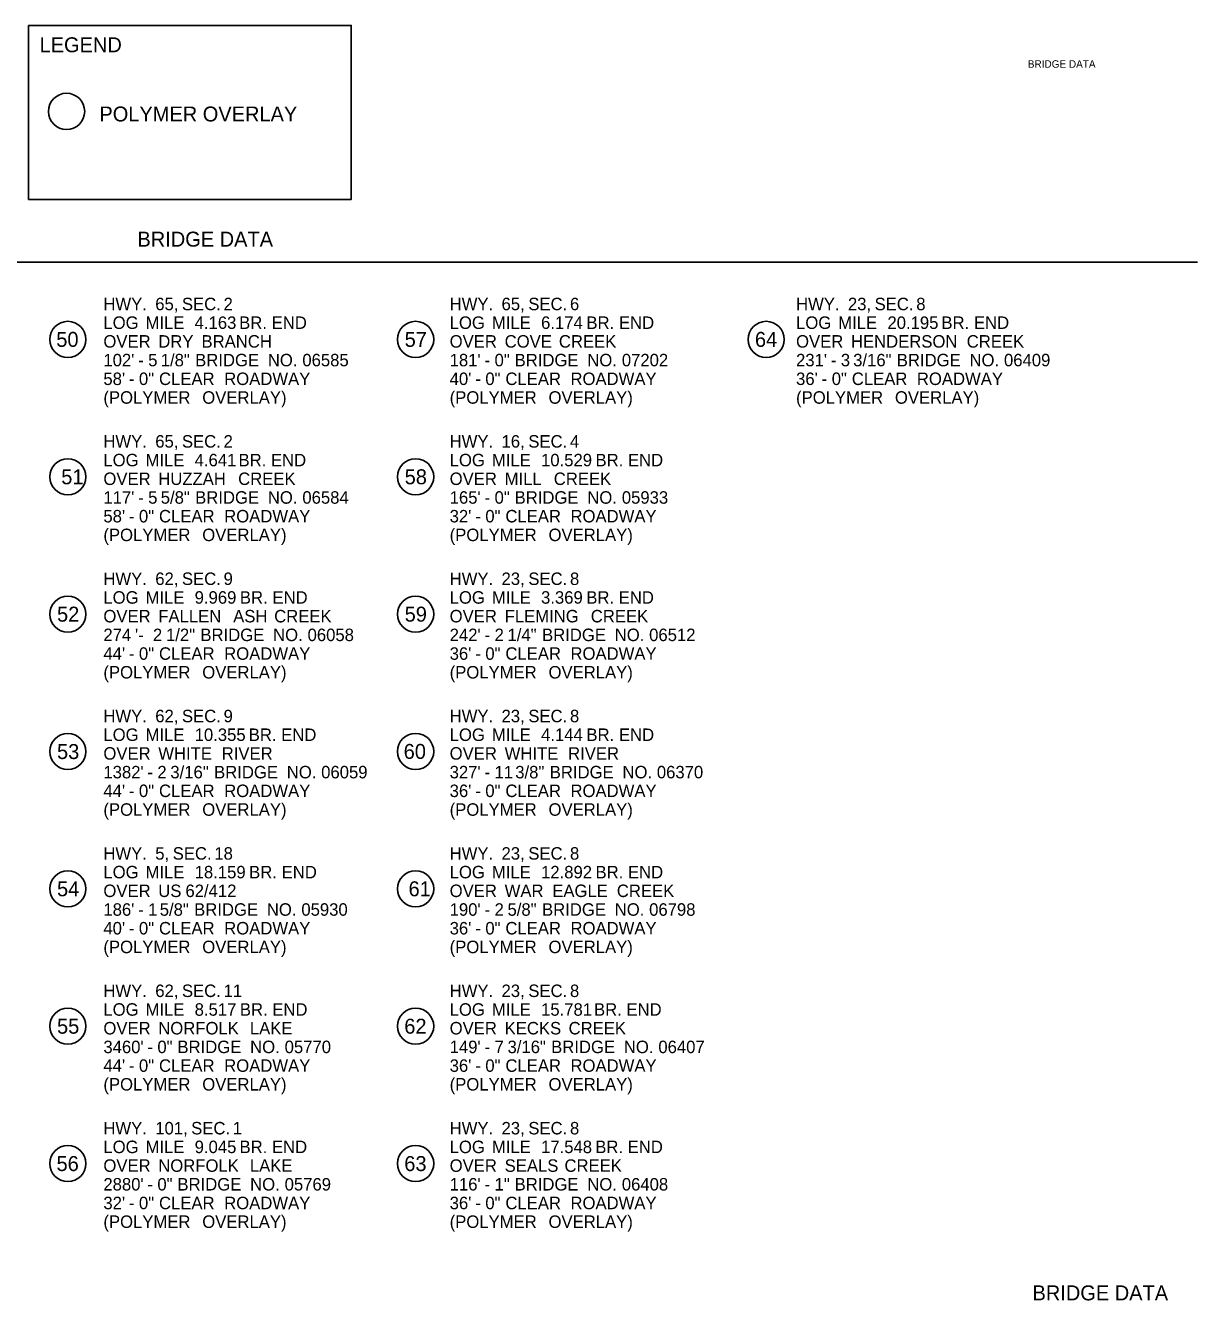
# Model space of a CAD drawing. Extents: x 1930546 to 1934225, y 596452 to 599553.
# Drawn here: x 1933284 to 1934225, y 598531 to 599553 of the extents above; entities that cross this region are included whole.
import ezdxf

# ---------------------------------------------------------------- set-up
doc = ezdxf.new("R2010")
doc.units = 0
for name, color, linetype in [('Default', 7, 'Continuous'), ('R_Border', 7, 'Continuous'), ('S_AREA_CALC', 7, 'Continuous')]:
    doc.layers.add(name, color=color, linetype=linetype)

msp = doc.modelspace()

# ---------------------------------------------------------------- linework, layer by layer
at = {"layer": 'R_Border'}
msp.add_line((1934224.6, 599363.5), (1932629.2, 599363.5), dxfattribs=at)
msp.add_lwpolyline([(1933286.8, 599553.3), (1933545.7, 599553.3), (1933545.7, 599413.8), (1933286.8, 599413.8)], close=True, dxfattribs=at)
for centre in [(1933317.3, 599484.4), (1933318.3, 599301.5), (1933597.3, 599301.5), (1933878.5, 599301.5), (1933318.3, 599191.3), (1933597.3, 599191.3), (1933318.3, 599081.1), (1933597.3, 599081.1), (1933318.3, 598970.9), (1933597.3, 598971), (1933318.3, 598860.8), (1933597.3, 598860.8), (1933318.3, 598750.6), (1933597.3, 598750.6), (1933318.3, 598640.4), (1933597.3, 598640.4)]:
    msp.add_circle(centre, 14.5, dxfattribs=at)

# ---------------------------------------------------------------- texts
at = {"layer": 'Default'}
for s, p in [('HWY.', (1933346.8, 599324.9)), (' 65,', (1933384.7, 599324.9)), (' SEC.', (1933406.1, 599324.9)), (' 2', (1933439.5, 599324.9)), ('HWY.', (1933624.6, 599324.9)), (' 65,', (1933662.5, 599324.9)), (' SEC.', (1933684, 599324.9)), (' 6', (1933717.4, 599324.9)), ('HWY.', (1933902.5, 599324.9)), (' 23,', (1933940.4, 599324.9)), (' SEC.', (1933961.8, 599324.9)), (' 8', (1933995.2, 599324.9)), ('LOG', (1933346.8, 599309.9)), (' MILE', (1933376.9, 599309.9)), (' 4.163', (1933416.3, 599309.9)), (' BR.', (1933452, 599309.9)), (' END', (1933478.1, 599309.9)), ('LOG', (1933624.6, 599309.9)), (' MILE', (1933654.8, 599309.9)), (' 6.174', (1933694.2, 599309.9)), (' BR.', (1933730.6, 599309.9)), (' END', (1933756.7, 599309.9)), ('LOG', (1933902.5, 599309.9)), (' MILE', (1933932.6, 599309.9)), (' 20.195', (1933972.1, 599309.9)), (' BR.', (1934015.4, 599309.9)), (' END', (1934041.5, 599309.9)), ('OVER', (1933346.8, 599294.9)), (' DRY', (1933387.1, 599294.9)), (' BRANCH', (1933421.8, 599294.9)), ('OVER', (1933624.6, 599294.9)), (' COVE', (1933665, 599294.9)), (' CREEK', (1933708.5, 599294.9)), ('OVER', (1933902.5, 599294.9)), (' HENDERSON', (1933942.8, 599294.9)), (' CREEK', (1934035.7, 599294.9)), ("102'", (1933346.8, 599279.9)), (' 5', (1933379, 599279.9)), (' 1/8"', (1933389.1, 599279.9)), (' BRIDGE', (1933416.7, 599279.9)), (' NO.', (1933475, 599279.9)), (' 06585', (1933502.7, 599279.9)), ("181'", (1933624.6, 599279.9)), (' 0"', (1933656.9, 599279.9)), (' BRIDGE', (1933673, 599279.9)), (' NO.', (1933731.3, 599279.9)), (' 07202', (1933759, 599279.9)), ("231'", (1933902.5, 599279.9)), (' 3', (1933934.7, 599279.9)), (' 3/16"', (1933944.6, 599279.9)), (' BRIDGE', (1933979.6, 599279.9)), (' NO.', (1934037.9, 599279.9)), (' 06409', (1934065.6, 599279.9)), (' -', (1933371, 599279.9)), (' -', (1933648.8, 599279.9)), (' -', (1933926.7, 599279.9)), ("58'", (1933346.8, 599264.9)), (' -', (1933363.6, 599264.9)), (' 0"', (1933371.6, 599264.9)), (' CLEAR', (1933387.7, 599264.9)), (' ROADWAY', (1933440, 599264.9)), ("40'", (1933624.6, 599264.9)), (' -', (1933641.5, 599264.9)), (' 0"', (1933649.5, 599264.9)), (' CLEAR', (1933665.6, 599264.9)), (' ROADWAY', (1933717.8, 599264.9)), ("36'", (1933902.5, 599264.9)), (' -', (1933919.3, 599264.9)), (' 0"', (1933927.4, 599264.9)), (' CLEAR', (1933943.5, 599264.9)), (' ROADWAY', (1933995.7, 599264.9)), ('(POLYMER', (1933346.8, 599249.9)), (' OVERLAY)', (1933422.4, 599249.9)), ('(POLYMER', (1933624.6, 599249.9)), (' OVERLAY)', (1933700.2, 599249.9)), ('(POLYMER', (1933902.5, 599249.9)), (' OVERLAY)', (1933978.1, 599249.9)), ('HWY.', (1933346.8, 599214.7)), (' 65,', (1933384.7, 599214.7)), (' SEC.', (1933406.1, 599214.7)), (' 2', (1933439.5, 599214.7)), ('HWY.', (1933624.6, 599214.7)), (' 16,', (1933662.5, 599214.7)), (' SEC.', (1933684, 599214.7)), (' 4', (1933717.4, 599214.7)), ('LOG', (1933346.8, 599199.7)), (' MILE', (1933376.9, 599199.7)), (' 4.641', (1933416.3, 599199.7)), (' BR.', (1933451.5, 599199.7)), (' END', (1933477.5, 599199.7)), ('LOG', (1933624.6, 599199.7)), (' MILE', (1933654.8, 599199.7)), (' 10.529', (1933694.2, 599199.7)), (' BR.', (1933737.9, 599199.7)), (' END', (1933763.9, 599199.7)), ('OVER', (1933346.8, 599184.7)), (' HUZZAH', (1933387.1, 599184.7)), (' CREEK', (1933451.2, 599184.7)), ('OVER', (1933624.6, 599184.7)), (' MILL', (1933665, 599184.7)), (' CREEK', (1933704.4, 599184.7)), ("117'", (1933346.8, 599169.7)), (' 5', (1933379, 599169.7)), (' 5/8"', (1933389.1, 599169.7)), (' BRIDGE', (1933416.7, 599169.7)), (' NO.', (1933475, 599169.7)), (' 06584', (1933502.7, 599169.7)), ("165'", (1933624.6, 599169.7)), (' 0"', (1933656.9, 599169.7)), (' BRIDGE', (1933673, 599169.7)), (' NO.', (1933731.3, 599169.7)), (' 05933', (1933759, 599169.7)), (' -', (1933371, 599169.7)), (' -', (1933648.8, 599169.7)), ("58'", (1933346.8, 599154.7)), (' -', (1933363.6, 599154.7)), (' 0"', (1933371.6, 599154.7)), (' CLEAR', (1933387.7, 599154.7)), (' ROADWAY', (1933440, 599154.7)), ("32'", (1933624.6, 599154.7)), (' -', (1933641.5, 599154.7)), (' 0"', (1933649.5, 599154.7)), (' CLEAR', (1933665.6, 599154.7)), (' ROADWAY', (1933717.8, 599154.7)), ('(POLYMER', (1933346.8, 599139.7)), (' OVERLAY)', (1933422.4, 599139.7)), ('(POLYMER', (1933624.6, 599139.7)), (' OVERLAY)', (1933700.2, 599139.7)), ('HWY.', (1933346.8, 599104.5)), (' 62,', (1933384.7, 599104.5)), (' SEC.', (1933406.1, 599104.5)), (' 9', (1933439.5, 599104.5)), ('HWY.', (1933624.6, 599104.5)), (' 23,', (1933662.5, 599104.5)), (' SEC.', (1933684, 599104.5)), (' 8', (1933717.4, 599104.5)), ('LOG', (1933346.8, 599089.5)), (' MILE', (1933376.9, 599089.5)), (' 9.969', (1933416.3, 599089.5)), (' BR.', (1933452.6, 599089.5)), (' END', (1933478.7, 599089.5)), ('LOG', (1933624.6, 599089.5)), (' MILE', (1933654.8, 599089.5)), (' 3.369', (1933694.2, 599089.5)), (' BR.', (1933730.5, 599089.5)), (' END', (1933756.5, 599089.5)), ('OVER', (1933346.8, 599074.5)), (' FALLEN', (1933387.1, 599074.5)), (' ASH', (1933447.2, 599074.5)), (' CREEK', (1933480.1, 599074.5)), ('OVER', (1933624.6, 599074.5)), (' FLEMING', (1933665, 599074.5)), (' CREEK', (1933734.1, 599074.5)), ('274', (1933346.8, 599059.5)), (" '-", (1933368.4, 599059.5)), ('  2', (1933379.1, 599059.5)), (' 1/2"', (1933393.3, 599059.5)), (' BRIDGE', (1933420.9, 599059.5)), (' NO.', (1933479.2, 599059.5)), (' 06058', (1933506.9, 599059.5)), ("242'", (1933624.6, 599059.5)), (' -', (1933648.8, 599059.5)), (' 2', (1933656.9, 599059.5)), (' 1/4"', (1933667.3, 599059.5)), (' BRIDGE', (1933695, 599059.5)), (' NO.', (1933753.3, 599059.5)), (' 06512', (1933780.9, 599059.5)), ("44'", (1933346.8, 599044.5)), (' 0"', (1933371.6, 599044.5)), (' CLEAR', (1933387.7, 599044.5)), (' ROADWAY', (1933440, 599044.5)), ("36'", (1933624.6, 599044.5)), (' 0"', (1933649.5, 599044.5)), (' CLEAR', (1933665.6, 599044.5)), (' ROADWAY', (1933717.8, 599044.5)), (' -', (1933363.6, 599044.5)), (' -', (1933641.5, 599044.5)), ('(POLYMER', (1933346.8, 599029.5)), (' OVERLAY)', (1933422.4, 599029.5)), ('(POLYMER', (1933624.6, 599029.5)), (' OVERLAY)', (1933700.2, 599029.5)), ('HWY.', (1933346.8, 598994.4)), (' 62,', (1933384.7, 598994.4)), (' SEC.', (1933406.1, 598994.4)), (' 9', (1933439.5, 598994.4)), ('HWY.', (1933624.6, 598994.4)), (' 23,', (1933662.5, 598994.4)), (' SEC.', (1933684, 598994.4)), (' 8', (1933717.4, 598994.4)), ('LOG', (1933346.8, 598979.4)), (' MILE', (1933376.9, 598979.4)), (' 10.355', (1933416.3, 598979.4)), (' BR.', (1933459.7, 598979.4)), (' END', (1933485.7, 598979.4)), ('LOG', (1933624.6, 598979.4)), (' MILE', (1933654.8, 598979.4)), (' 4.144', (1933694.2, 598979.4)), (' BR.', (1933730.6, 598979.4)), (' END', (1933756.7, 598979.4)), ('OVER', (1933346.8, 598964.4)), (' WHITE', (1933387.1, 598964.4)), (' RIVER', (1933438, 598964.4)), ('OVER', (1933624.6, 598964.4)), (' WHITE', (1933665, 598964.4)), (' RIVER', (1933715.9, 598964.4)), ("1382'", (1933346.8, 598949.4)), (' -', (1933378.4, 598949.4)), (' 2', (1933386.4, 598949.4)), (' 3/16"', (1933396.8, 598949.4)), (' BRIDGE', (1933431.9, 598949.4)), (' NO.', (1933490.2, 598949.4)), (' 06059', (1933517.8, 598949.4)), ("327'", (1933624.6, 598949.4)), (' -', (1933648.8, 598949.4)), (' 11', (1933656.9, 598949.4)), (' 3/8"', (1933673.5, 598949.4)), (' BRIDGE', (1933701.2, 598949.4)), (' NO.', (1933759.5, 598949.4)), (' 06370', (1933787.1, 598949.4)), ("44'", (1933346.8, 598934.4)), (' 0"', (1933371.6, 598934.4)), (' CLEAR', (1933387.7, 598934.4)), (' ROADWAY', (1933440, 598934.4)), ("36'", (1933624.6, 598934.4)), (' 0"', (1933649.5, 598934.4)), (' CLEAR', (1933665.6, 598934.4)), (' ROADWAY', (1933717.8, 598934.4)), (' -', (1933363.6, 598934.4)), (' -', (1933641.5, 598934.4)), ('(POLYMER', (1933346.8, 598919.4)), (' OVERLAY)', (1933422.4, 598919.4)), ('(POLYMER', (1933624.6, 598919.4)), (' OVERLAY)', (1933700.2, 598919.4)), ('HWY.', (1933346.8, 598884.2)), (' 5,', (1933384.7, 598884.2)), (' SEC.', (1933398.7, 598884.2)), (' 18', (1933432.1, 598884.2)), ('HWY.', (1933624.6, 598884.2)), (' 23,', (1933662.5, 598884.2)), (' SEC.', (1933684, 598884.2)), (' 8', (1933717.4, 598884.2)), ('LOG', (1933346.8, 598869.2)), (' MILE', (1933376.9, 598869.2)), (' 18.159', (1933416.3, 598869.2)), (' BR.', (1933460, 598869.2)), (' END', (1933486.1, 598869.2)), ('LOG', (1933624.6, 598869.2)), (' MILE', (1933654.8, 598869.2)), (' 12.892', (1933694.2, 598869.2)), (' BR.', (1933737.9, 598869.2)), (' END', (1933763.9, 598869.2)), ('OVER', (1933346.8, 598854.2)), (' US', (1933387.1, 598854.2)), (' 62/412', (1933408.9, 598854.2)), ('OVER', (1933624.6, 598854.2)), (' WAR', (1933665, 598854.2)), (' EAGLE', (1933703.2, 598854.2)), (' CREEK', (1933755, 598854.2)), ("186'", (1933346.8, 598839.2)), (' 1', (1933379, 598839.2)), (' 5/8"', (1933388.3, 598839.2)), (' BRIDGE', (1933415.9, 598839.2)), (' NO.', (1933474.2, 598839.2)), (' 05930', (1933501.9, 598839.2)), ("190'", (1933624.6, 598839.2)), (' 2', (1933656.9, 598839.2)), (' 5/8"', (1933667.3, 598839.2)), (' BRIDGE', (1933695, 598839.2)), (' NO.', (1933753.3, 598839.2)), (' 06798', (1933780.9, 598839.2)), (' -', (1933371, 598839.2)), (' -', (1933648.8, 598839.2)), ("40'", (1933346.8, 598824.2)), (' -', (1933363.6, 598824.2)), (' 0"', (1933371.6, 598824.2)), (' CLEAR', (1933387.7, 598824.2)), (' ROADWAY', (1933440, 598824.2)), ("36'", (1933624.6, 598824.2)), (' -', (1933641.5, 598824.2)), (' 0"', (1933649.5, 598824.2)), (' CLEAR', (1933665.6, 598824.2)), (' ROADWAY', (1933717.8, 598824.2)), ('(POLYMER', (1933346.8, 598809.2)), (' OVERLAY)', (1933422.4, 598809.2)), ('(POLYMER', (1933624.6, 598809.2)), (' OVERLAY)', (1933700.2, 598809.2)), ('HWY.', (1933346.8, 598774)), (' 62,', (1933384.7, 598774)), (' SEC.', (1933406.1, 598774)), (' 11', (1933439.5, 598774)), ('HWY.', (1933624.6, 598774)), (' 23,', (1933662.5, 598774)), (' SEC.', (1933684, 598774)), (' 8', (1933717.4, 598774)), ('LOG', (1933346.8, 598759)), (' MILE', (1933376.9, 598759)), (' 8.517', (1933416.3, 598759)), (' BR.', (1933452.6, 598759)), (' END', (1933478.6, 598759)), ('LOG', (1933624.6, 598759)), (' MILE', (1933654.8, 598759)), (' 15.781', (1933694.2, 598759)), (' BR.', (1933736.7, 598759)), (' END', (1933762.7, 598759)), ('OVER', (1933346.8, 598744)), (' NORFOLK', (1933387.1, 598744)), (' LAKE', (1933460.6, 598744)), ('OVER', (1933624.6, 598744)), (' KECKS', (1933665, 598744)), (' CREEK', (1933716.3, 598744)), ("3460'", (1933346.8, 598729)), (' 0"', (1933386.4, 598729)), (' BRIDGE', (1933402.5, 598729)), (' NO.', (1933460.8, 598729)), (' 05770', (1933488.5, 598729)), ("149'", (1933624.6, 598729)), (' 7', (1933656.9, 598729)), (' 3/16"', (1933667.3, 598729)), (' BRIDGE', (1933702.3, 598729)), (' NO.', (1933760.6, 598729)), (' 06407', (1933788.3, 598729)), (' -', (1933378.4, 598729)), (' -', (1933648.8, 598729)), ("44'", (1933346.8, 598714)), (' -', (1933363.6, 598714)), (' 0"', (1933371.6, 598714)), (' CLEAR', (1933387.7, 598714)), (' ROADWAY', (1933440, 598714)), ("36'", (1933624.6, 598714)), (' -', (1933641.5, 598714)), (' 0"', (1933649.5, 598714)), (' CLEAR', (1933665.6, 598714)), (' ROADWAY', (1933717.8, 598714)), ('(POLYMER', (1933346.8, 598699)), (' OVERLAY)', (1933422.4, 598699)), ('(POLYMER', (1933624.6, 598699)), (' OVERLAY)', (1933700.2, 598699)), ('HWY.', (1933346.8, 598663.8)), (' 101,', (1933384.7, 598663.8)), (' SEC.', (1933413.5, 598663.8)), (' 1', (1933446.9, 598663.8)), ('HWY.', (1933624.6, 598663.8)), (' 23,', (1933662.5, 598663.8)), (' SEC.', (1933684, 598663.8)), (' 8', (1933717.4, 598663.8)), ('LOG', (1933346.8, 598648.8)), (' MILE', (1933376.9, 598648.8)), (' 9.045', (1933416.3, 598648.8)), (' BR.', (1933452.3, 598648.8)), (' END', (1933478.3, 598648.8)), ('LOG', (1933624.6, 598648.8)), (' MILE', (1933654.8, 598648.8)), (' 17.548', (1933694.2, 598648.8)), (' BR.', (1933737.7, 598648.8)), (' END', (1933763.7, 598648.8)), ('OVER', (1933346.8, 598633.8)), (' NORFOLK', (1933387.1, 598633.8)), (' LAKE', (1933460.6, 598633.8)), ('OVER', (1933624.6, 598633.8)), (' SEALS', (1933665, 598633.8)), (' CREEK', (1933713, 598633.8)), ("2880'", (1933346.8, 598618.8)), (' 0"', (1933386.4, 598618.8)), (' BRIDGE', (1933402.5, 598618.8)), (' NO.', (1933460.8, 598618.8)), (' 05769', (1933488.5, 598618.8)), ("116'", (1933624.6, 598618.8)), (' 1"', (1933656.9, 598618.8)), (' BRIDGE', (1933673, 598618.8)), (' NO.', (1933731.3, 598618.8)), (' 06408', (1933759, 598618.8)), ("32'", (1933346.8, 598603.8)), (' 0"', (1933371.6, 598603.8)), (' -', (1933378.4, 598618.8)), (' CLEAR', (1933387.7, 598603.8)), (' ROADWAY', (1933440, 598603.8)), ("36'", (1933624.6, 598603.8)), (' -', (1933648.8, 598618.8)), (' 0"', (1933649.5, 598603.8)), (' CLEAR', (1933665.6, 598603.8)), (' ROADWAY', (1933717.8, 598603.8)), (' -', (1933363.6, 598603.8)), (' -', (1933641.5, 598603.8)), ('(POLYMER', (1933346.8, 598588.8)), (' OVERLAY)', (1933422.4, 598588.8)), ('(POLYMER', (1933624.6, 598588.8)), (' OVERLAY)', (1933700.2, 598588.8))]:
    msp.add_text(s, height=10, dxfattribs=at).set_placement(p)
at = {"layer": 'R_Border'}
for s, p in [('LEGEND', (1933295.6, 599531.8)), ('POLYMER OVERLAY', (1933343.6, 599476.3)), ('BRIDGE DATA', (1933374.1, 599375.9)), ('50', (1933309, 599295.5)), ('57', (1933588.5, 599295.5)), ('64', (1933869.5, 599295.5)), ('51', (1933313, 599185.3)), ('58', (1933588.5, 599185.3)), ('52', (1933309.6, 599075.1)), ('59', (1933588.5, 599075.1)), ('53', (1933309.6, 598964.9)), ('60', (1933587.7, 598965)), ('54', (1933309.6, 598854.8)), ('61', (1933591.6, 598854.8)), ('55', (1933309.6, 598744.6)), ('62', (1933588.2, 598744.6)), ('56', (1933309.2, 598634.4)), ('63', (1933588.2, 598634.4)), ('BRIDGE DATA', (1934092.2, 598530.7))]:
    msp.add_text(s, height=12, rotation=360, dxfattribs=at).set_placement(p)
at = {"layer": 'S_AREA_CALC'}
msp.add_text('BRIDGE DATA', height=6, rotation=360, dxfattribs=at).set_placement((1934088.4, 599519.4))

doc.saveas('drawing.dxf')
